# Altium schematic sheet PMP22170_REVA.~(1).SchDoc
size 431 x 279 mm; Date: Not shown in title block; ApprovedBy: Not shown in title block; CheckedBy: Not shown in title block; Author: Not shown in title block; CompanyName: Not shown in title block; Engineer: Not shown in title block; Organization: Not shown in title block; Address1: Not shown in title block; Address2: Not shown in title block; Address3: Not shown in title block; Address4: Not shown in title block; DocumentNumber: 2; Revision: Use project parameter SCH_Rev; SheetNumber: 2; SheetTotal: 3; PageSetup: Record=PageOptions¦CenterHorizontal=True¦CenterVertical=True¦PrintScale=1.00¦XCorrection=1.00¦YCorrection=1.00¦PrintKind=0¦BorderSize=5000000¦LeftOffset=0¦BottomOffset=0¦Orientation=2¦PaperLength=1000¦PaperWidth=1000¦Scale=100¦PaperSource=15¦PrintQuality=600¦MediaType=1¦DitherType=10¦PaperKind=Letter¦PrintScaleMode=1
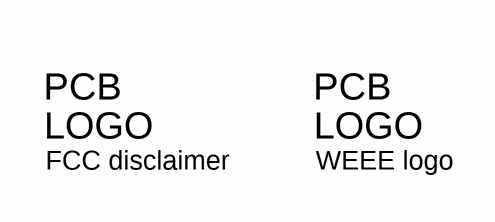
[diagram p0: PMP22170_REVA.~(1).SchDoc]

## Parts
(Parts that share a designator on the sheet are numbered #1, #2 ... from top to bottom, then left to right.)
Logo?#1  FCC disclaimer  [FCC_disclaimer]  (no BOM)
Logo?#2  WEEE logo  [WEEE_Minimum]  (no BOM)

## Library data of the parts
Logo?#1 = CMP-0074847-1: FCC_disclaimer; Library Reference: Logo
Logo?#2 = CMP-0074769-1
